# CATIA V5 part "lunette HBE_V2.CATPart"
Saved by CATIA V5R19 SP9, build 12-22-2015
Part number: Part1
Bounding box of the stored display mesh (mm): x -68 to 68, y -20 to 123.291, z -28.492 to 28.495
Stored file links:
  C:\Users\hbezard\Documents\Perso\imprimante 3d\pieces\lunette transport\lunette HBE_V2.CATPart
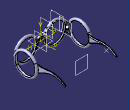
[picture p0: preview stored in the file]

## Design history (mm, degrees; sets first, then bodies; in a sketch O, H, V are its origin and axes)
Set1
  Plane1: type Offset, RefPlane zx-plane, Offset 100
  Plane2: type Offset, RefPlane yz-plane, Offset 60, reversed
  Point1: (-60, 100, 0)
  Line1: type PtDir, RefPoint {point type Coord, X -35, Y 0, Z 0}, Direction (0, 1, 0), Start 0, End 20
  Plane3: type Normal, Curve Sketch14, RefPoint Sketch14.P6
  Plane4: type OffsetPt, RefPlane yz-plane, RefPoint vertex of Line1
Body1 (main body)
  Sketch1 on zx-plane, origin (0, 0, 0), H (0, 0, 1), V (1, 0, 0)
    point P1 (-13, 0)
    line L1 (-13, 0) -> (-13, -9)
    line L2 (-13, -9) -> (1.4, -4.8)
    arc A1 centre (0, 0) radius 5 from (1.4, -4.8) to (5, 0) ccw
    point P4 (0, 0)
    point P5 (5, 0)
    line L3 (5, 0) -> (-13, 0)
    reference intersected line E1 through (0, 0) direction (0, 1) from xy-plane
    length L2 = 15
    length L1 = 9
    radius A1 = 5
    coincidence: P1 H, P5 H, P4 L3, P4 E1
    vertical: L1 V
    tangency: A1 L2
    horizontal: L3 H
  Pad1: profile Sketch1, direction (0, 1, 0), length 5, mirrored extent
  Sketch2 on Plane2, origin (-60, 0, 0), H (0, 1, 0), V (0, 0, 1)
    circle A1 centre (100, 0) radius 10
    reference projected point E1 (100, 0) from Point1
    radius A1 = 10
    concentricity: A1 E1
  Pad2: profile Sketch2, direction (1, 0, 0), length 5, mirrored extent
  Sketch3 on xy-plane, origin (0, 0, 0), H (1, 0, 0), V (0, 1, 0)
    arc A1 centre (-9.5, 0) radius 3 from (-6.5, 0) to (-11, 2.5981) ccw
    point P1 (-9.5, 0)
    arc A2 centre (-12.5, 0) radius 3 from (-9.5, 0) to (-11, 2.5981) ccw
    point P2 (-12.5, 0)
    reference intersected line E1 through (0, 0) direction (-1, 0) from zx-plane
    reference intersected line E2 through (0, 0) direction (-1, 0) from zx-plane
    axis line L1 (-35, 5.0345) -> (-35, -8.3344)
    arc A3 centre (-9.5, 0) radius 3 from (-11, -2.5981) to (-6.5, 0) ccw
    point P5 (-6.5, 0)
    point P6 (-6.5, 0)
    arc A4 centre (-12.5, 0) radius 3 from (-11, -2.5981) to (-9.5, 0) ccw
    point P7 (-9.5, 0)
    point P8 (-9.5, 0)
    reference projected line E3 (-35, -20) -> (-35, 0) from Line1
    distance P2 P1 = 3
    radius A2 = 3
    radius A1 = 3
    distance L1 P2 = 22.5
    coincidence: P2 E1, P1 E2, A1 A3, A2 A4, L1 E3, P5 P6, P7 P8
    vertical: L1 V
Body2
  Sketch4 on xy-plane, origin (0, 0, 0), H (1, 0, 0), V (0, 1, 0)
    arc A1 centre (-9.5, 0) radius 3 from (-6.5, 0) to (-11, 2.5981) ccw
    point P1 (-9.5, 0)
    arc A2 centre (-12.5, 0) radius 3 from (-9.5, 0) to (-11, 2.5981) ccw
    point P2 (-12.5, 0)
    reference intersected line E1 through (0, 0) direction (-1, 0) from zx-plane
    reference intersected line E2 through (0, 0) direction (-1, 0) from zx-plane
    axis line L1 (-35, 5.0345) -> (-35, -8.3344)
    arc A3 centre (-9.5, 0) radius 3 from (-11, -2.5981) to (-6.5, 0) ccw
    point P5 (-6.5, 0)
    point P6 (-6.5, 0)
    arc A4 centre (-12.5, 0) radius 3 from (-11, -2.5981) to (-9.5, 0) ccw
    point P7 (-9.5, 0)
    point P8 (-9.5, 0)
    reference projected line E3 (-35, -20) -> (-35, 0) from Line1
    distance P2 P1 = 3
    radius A2 = 3
    radius A1 = 3
    distance L1 P2 = 22.5
    coincidence: P2 E1, P1 E2, A1 A3, A2 A4, L1 E3, P5 P6, P7 P8
    vertical: L1 V
  Shaft1: profile Sketch4, axis Sketch4.L1, angle 360
  Sketch5 on xy-plane, origin (0, 0, 0), H (1, 0, 0), V (0, 1, 0)
    arc A1 centre (-65, 5) radius 3 from (-62.0114, 4.7389) to (-62.4019, 6.5) ccw
    point P1 (-65, 5)
    point P2 (-65, 8)
    construction line L1 (-65, 28.8094) -> (-65, 9.3354)
    arc A2 centre (-65, 5) radius 3 from (-67.5981, 6.5) to (-62.0114, 4.7389) ccw
    point P5 (-62.0114, 4.7389)
    point P6 (-62.0114, 4.7389)
    arc A3 centre (-65, 8) radius 3 from (-67.5981, 6.5) to (-62.4019, 6.5) ccw
    axis line L2 (-77.6916, 30.5) -> (-47.473, 30.5)
    reference intersected line E1 through (0, 0) direction (-1, 0) from zx-plane
    reference intersected line E2 through (-60, 0) direction (0, 1) from Plane2
    distance P2 P1 = 3
    radius A1 = 3
    distance A2 E1 = 2
    radius A3 = 3
    distance P2 L2 = 22.5
    distance E2 L1 = 5
    perpendicularity: L2 L1
    coincidence: P6 P5, P2 L1, P1 L1
  Shaft2: profile Sketch5, axis Sketch5.L2, angle 360
  Sketch6 on zx-plane, origin (0, 0, 0), H (0, 0, 1), V (1, 0, 0)
    spline S1 through (2.4075, -9.9617) (11.1803, -1.4145) (11.2076, 0)
    spline S2 through (-14.8925, -14.4686) (-0.4937, -5.9056) (6.4476, -1.5195) (6.5002, 0)
    line L1 (6.5002, 0) -> (11.2076, 0)
    point P1 (6.5002, 0)
    point P2 (11.2076, 0)
    construction circle A1 centre (0, -35) radius 28.5
    construction unspec C1
    construction unspec C2
    point P7 (0, -35)
    construction circle A2 centre (0, -35) radius 25.5
    arc A3 centre (0, -35) radius 25.5 from (3.1869, -9.6999) to (-14.8594, -14.2768) ccw
    point P8 (11.2076, 0)
    point P9 (6.5002, 0)
    coincidence: P8 H, P9 H, P9 P1, P8 P2
    horizontal: L1 H
  Pad3: profile Sketch6, direction (0, 1, 0), length 3, mirrored extent
  Fillet1: radius 9, on edge [start face of Pad3 | face of Shaft1 from Sketch4.A3], deactivated
  Fillet2: radius 2.21, on edge [face of Pad3 from Sketch6.S2 | end face of Pad3]
  Fillet3: radius 0.5, on edge [start face of Pad3 | face of Pad3 from Sketch6.S2]
  Fillet4: radius 0.5, on edge [face of Pad3 from Sketch6.S1 | end face of Pad3]; edge [start face of Pad3 | face of Pad3 from Sketch6.S1]
  Fillet5: radius 0.5, on edge [face of Pad3 from Sketch6.S1 | face of Shaft1]
  Sketch7 on Plane2, origin (-60, 0, 0), H (0, 1, 0), V (0, 0, 1)
    projected circle E1 centre (30.5, 0) radius 25.7611 from edge [face of Shaft2 from Sketch5.A2 | face of Shaft2 from Sketch5.A1]
    projected arc E2 centre (30.5, 0) radius 25.7611 from (54.9278, -8.1802) to (53.6014, 11.3998) ccw from edge [face of Shaft2 from Sketch5.A2 | face of Shaft2 from Sketch5.A1]
    spline S1 through (120.7443, -3.2439) (108.1104, 3.6342) (99.8681, 6.0232) (82.2912, 4.3598) (71.607, 0.0892) (56.7554, -7.2965) (49.9444, -10.4984)
    spline S2 through (122.5651, -0.5495) (114.045, 4.4898) (99.9307, 9.7686) (57.7285, 9.9348) (49.9341, 13.3072)
    arc A1 centre (121.6645, -1.9033) radius 1.626 from (120.7443, -3.2439) to (122.5651, -0.5495) ccw
    point P3 (120.7443, -3.2439)
    point P4 (122.5651, -0.5495)
    point P8 (120.7443, -3.2439)
    point P9 (122.5651, -0.5495)
    coincidence: P8 P3, P9 P4
    tangency: A1 S1, A1 S2
  Pad4: profile Sketch7, direction (-1, 0, 0), length 3
  Fillet6: radius 2, on edge [face of Pad4 from Sketch7.E2 | face of Shaft2 from Sketch5.A1]
  Fillet7: radius 1.5, on edge [face of Pad4 from Sketch7.E2 | start face of Pad4]
  Fillet8: radius 1.5, on edge [face of Pad4 from Sketch7.S2 | start face of Pad4]
  Fillet9: radius 1.5, on end face of Pad4, deactivated
  Sketch8 on xy-plane, origin (0, 0, 0), H (1, 0, 0), V (0, 1, 0)
    construction arc A1 centre (-60.5, 0) radius 3 from (-59, 2.5981) to (-59, -2.5981) ccw
    construction arc A2 centre (-9.5, 0) radius 3 from (-11, -2.5981) to (-11, 2.5981) ccw
    point P5 (-11, -2.5981)
    point P6 (-11, 2.5981)
    construction arc A3 centre (-9.5, 0) radius 3 from (-11, -2.5981) to (-11, 2.5981) ccw
    point P7 (-11, -2.5981)
    point P8 (-11, 2.5981)
    construction arc A4 centre (-65, 5) radius 3 from (-67.5981, 6.5) to (-62.4019, 6.5) ccw
    construction arc A5 centre (-65, 56) radius 3 from (-62.4019, 54.5) to (-67.5981, 54.5) ccw
    point P11 (-62.4019, 54.5)
    point P12 (-67.5981, 54.5)
    construction arc A6 centre (-65, 56) radius 3 from (-62.4019, 54.5) to (-67.5981, 54.5) ccw
    point P13 (-62.4019, 54.5)
    point P14 (-67.5981, 54.5)
    construction circle A7 centre (-62.0303, 3.1477) radius 0.5
    circle A8 centre (-62.0303, 3.1477) radius 2.15
    radius A7 = 0.5
    radius A8 = 2.15
    fix: A4, A1
    tangency: A7 A1, A7 A4
    concentricity: A8 A7
    coincidence: P5 P7, P6 P8, P11 P13, P12 P14
  Pocket1: profile Sketch8, direction (0, 0, -1), length 20, mirrored extent
  Sketch9 on xy-plane, origin (0, 0, 0), H (1, 0, 0), V (0, 1, 0)
    circle A1 centre (-62.0303, 3.1477) radius 1.1
    projected arc E1 centre (-62.0303, 3.1477) radius 2.15 from (-59.8854, 3) to (-63.1865, 1.3351) cw from edge [face of Shaft1 | face of Pocket1 from Sketch8.A8]
    projected arc E2 centre (-62.0303, 3.1477) radius 2.15 from (-59.8905, 2.9385) to (-63.1865, 1.3351) cw from edge [face of Shaft1 | face of Pocket1 from Sketch8.A8]
    point P3 (-63.1865, 1.3351)
    arc A2 centre (-59.7804, 3.1629) radius 0.25 from (-60.0304, 3.1612) to (-59.8905, 2.9385) ccw
    arc A3 centre (-63.4311, 1.387) radius 0.25 from (-63.1865, 1.3351) to (-63.2755, 1.5826) ccw
    arc A4 centre (-62.0303, 3.1477) radius 2 from (-60.0304, 3.1612) to (-63.2755, 1.5826) ccw
    reference projected point E3 (-62.0303, 3.1477) from axis of face of Pocket1 from Sketch8.A8
    point P8 (-59.8905, 2.9385)
    reference projected arc E4 centre (-62.0303, 3.1477) radius 2.15 from (-63.1865, 1.3351) to (-59.8854, 3) ccw from edge [face of Shaft1 | face of Pocket1 from Sketch8.A8]
    radius A1 = 1.1
    radius E1 = 2.15 (reference)
    radius A4 = 2
    radius A2 = 0.25
    radius A3 = 0.25
    concentricity: A4 E3
    coincidence: A3 P3, P8 E4
    tangency: A2 A4, A3 A4
  Pad5: profile Sketch9, direction (0, 0, 1), length 4, mirrored extent
  Sketch10 on xy-plane, origin (0, 0, 0), H (1, 0, 0), V (0, 1, 0)
    circle A1 centre (-62.0303, 3.1477) radius 1.5
    reference projected point E1 (-62.0303, 3.1477) from axis of face of Pocket1 from Sketch8.A8
    radius A1 = 1.5
    concentricity: A1 E1
  Sketch11 on xy-plane, origin (0, 0, 0), H (1, 0, 0), V (0, 1, 0)
    arc A1 centre (-62.0303, 3.1477) radius 2 from (-63.6747, 2.0094) to (-61.6461, 5.1105) ccw
    point P2 (-61.9992, 5.3816)
    point P3 (-64.0749, 2.2246)
    arc A2 centre (-61.55, 5.6011) radius 0.5 from (-61.8996, 5.2436) to (-61.6461, 5.1105) ccw
    arc A3 centre (-64.0858, 1.7248) radius 0.5 from (-63.6747, 2.0094) to (-63.8983, 2.1883) ccw
    point P10 (-62.0303, 3.1477)
    construction arc A4 centre (-62.859, 3.686) radius 1.9011 from (-61.9992, 5.3816) to (-64.0749, 2.2246) ccw
    arc A5 centre (-62.0303, 3.1477) radius 2.1 from (-61.8996, 5.2436) to (-63.8983, 2.1883) ccw
    reference projected point E1 (-62.0303, 3.1477) from axis of face of Pocket1 from Sketch8.A8
    radius A1 = 2
    radius A3 = 0.5
    radius A2 = 0.5
    radius A3 = 0.5 (reference)
    radius A5 = 2.1
    concentricity: A1 P10, A5 E1, A1 A5
    coincidence: A2 P2, A3 P3
    tangency: A2 A1, A3 A1
  Pad6: profile Sketch11, direction (0, 0, 1), length 11, opposite side length -4.2
  Pad7: profile Sketch11, direction (0, 0, -1), length 11, opposite side length -4.2
  Sketch12 on xy-plane, origin (0, 0, 0), H (1, 0, 0), V (0, 1, 0)
    circle A1 centre (-62.0303, 3.1477) radius 1
    reference projected point E1 (-62.0303, 3.1477) from axis of face of Pad6 from Sketch11.A5
    radius A1 = 1
    concentricity: A1 E1
  Pad8: profile Sketch12, direction (0, 0, 1), length 10, mirrored extent
  Sketch13 on xy-plane, origin (0, 0, 0), H (1, 0, 0), V (0, 1, 0)
    circle A1 centre (-62.0306, 3.1477) radius 0.5
    reference projected arc E1 centre (-62.0306, 3.1477) radius 2.1498 from (-62, 5.2973) to (-63.9476, 2.1748) ccw from edge [face of Shaft2 | face of Pocket1 from Sketch8.A8]
    radius A1 = 0.5
    concentricity: A1 E1
  Mirror1: of the body so far, about yz-plane
Body3
  Sketch14 on zx-plane, origin (0, 0, 0), H (-1, 0, 0), V (0, 0, 1)
    arc A1 centre (35, 0) radius 22.5 from (38.9071, 22.1582) to (31.0929, 22.1582) ccw
    point P1 (35, 0)
    reference projected point E1 (35, 0) from vertex of Line1
    reference projected circle E2 centre (35, 0) radius 25.5 from edge [face of Shaft1 from Sketch4.A4 | face of Shaft1 from Sketch4.A2]
    axis line L1 (35, 7.5958) -> (35, -7.5958)
    construction line L2 (35, 0) -> (31.0929, 22.1582)
    point P4 (35, 0)
    construction line L3 (35, 0) -> (38.9071, 22.1582)
    point P6 (38.9071, 22.1582)
    distance A1 E2 = 3
    angle L2 L1 = 10
    coincidence: P1 E1
    vertical: L1 V
    midpoint: L1 P1
    symmetry: P1 P4 L1, L2 L3 L1
  Sketch15 on Plane4, origin (-35, -20, 0), H (0, 1, 0), V (0, 0, 1)
    circle A1 centre (20, 22.5) radius 0.5
    point P1 (20, 22.5)
    circle A2 centre (20, 22.5) radius 1.5
    point P2 (20, 22.5)
    radius A1 = 0.5
    radius A2 = 1.5
    radius A2 = 1.5 (reference)
    coincidence: P1 P2
  Shaft3: profile Sketch15, axis Line1, angle 10, second angle 10
  Chamfer1: length 1, angle 30, on edge [face of Shaft3 | face of Shaft3 from Sketch15.A2]
  Chamfer2: length 1, angle 30, on edge [face of Shaft3 from Sketch15.A2 | face of Shaft3]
